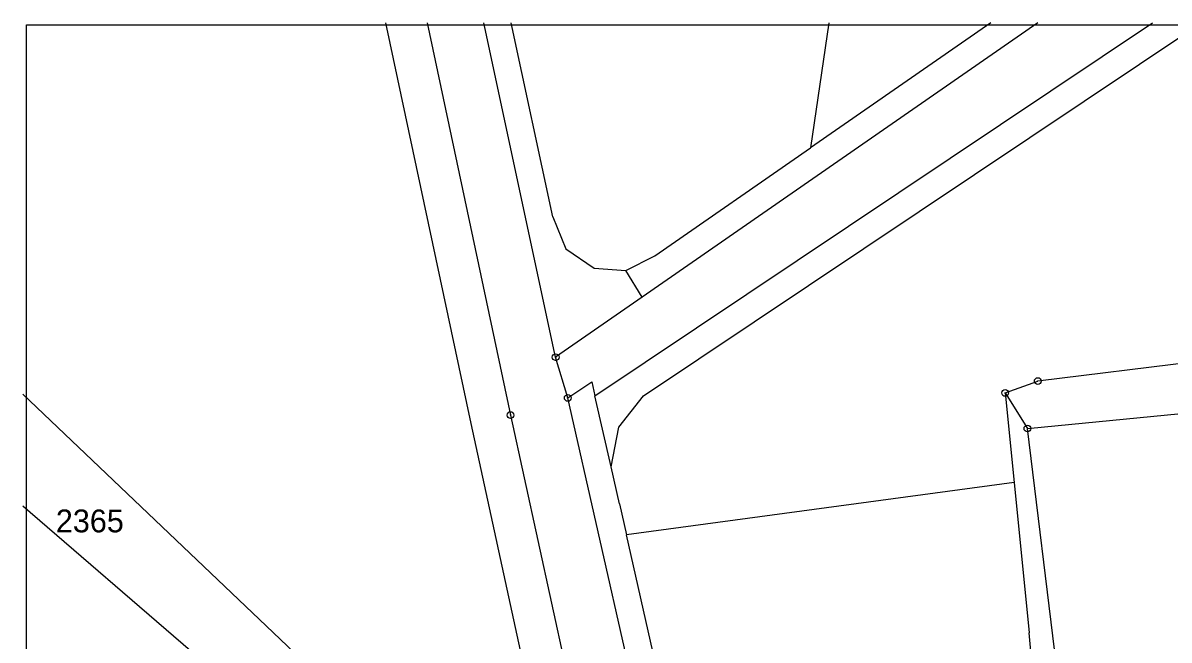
# Model space of a CAD drawing. Extents: x -566461 to -565198, y -1096301 to -1095707.
# Drawn here: x -566458.9 to -566288.3, y -1095798.6 to -1095706.8 of the extents above; entities that cross this region are included whole.
import ezdxf

# ---------------------------------------------------------------- set-up
doc = ezdxf.new("R2010")
doc.units = 0
for name, color, linetype in [('Vrstva 1', 7, 'Continuous'), ('Vrstva 18', 7, 'Continuous'), ('Vrstva 24', 7, 'Continuous'), ('Vrstva 63', 7, 'Continuous')]:
    doc.layers.add(name, color=color, linetype=linetype)

msp = doc.modelspace()

# ---------------------------------------------------------------- linework, layer by layer
at = {"layer": 'Vrstva 1'}
for p, q in [((-566392.21, -1095766.39), (-566404.9, -1095706.75)), ((-566398.76, -1095706.75), (-566386.34, -1095765.13)), ((-566379.63, -1095756.52), (-566390.34, -1095706.75)), ((-566380.04, -1095735.62), (-566386.25, -1095706.75)), ((-566373.79, -1095762.26), (-566290.81, -1095706.75)), ((-566307.87, -1095706.75), (-566366.74, -1095747.58)), ((-566366.58, -1095762.27), (-566283.62, -1095706.75)), ((-566338.96, -1095706.75), (-566341.69, -1095725.34)), ((-566314.89, -1095706.75), (-566341.69, -1095725.34)), ((-566364.89, -1095741.43), (-566341.69, -1095725.34)), ((-566380.04, -1095735.62), (-566378.1, -1095740.37)), ((-566378.1, -1095740.37), (-566373.9, -1095743.25)), ((-566369.18, -1095743.6), (-566364.89, -1095741.43)), ((-566373.9, -1095743.25), (-566369.18, -1095743.6)), ((-566366.74, -1095747.58), (-566369.18, -1095743.6)), ((-566366.74, -1095747.58), (-566379.63, -1095756.52)), ((-566377.83, -1095762.58), (-566379.63, -1095756.52)), ((-566277.86, -1095756.39), (-566307.89, -1095760.07)), ((-566377.83, -1095762.58), (-566374.26, -1095760.19)), ((-566374.26, -1095760.19), (-566373.79, -1095762.26)), ((-566312.74, -1095761.84), (-566307.89, -1095760.07)), ((-566458.91, -1095762.04), (-566383.43, -1095833.87)), ((-566312.74, -1095761.84), (-566309.42, -1095767.13)), ((-566312.74, -1095761.84), (-566311.41, -1095775.18)), ((-566342.24, -1095919.36), (-566377.83, -1095762.58)), ((-566371.39, -1095772.85), (-566373.79, -1095762.26)), ((-566370.23, -1095766.91), (-566366.58, -1095762.27)), ((-566386.34, -1095765.13), (-566359.94, -1095886.56)), ((-566309.42, -1095767.13), (-566276.83, -1095763.96)), ((-566376.68, -1095837.78), (-566392.21, -1095766.39)), ((-566371.39, -1095772.85), (-566370.23, -1095766.91)), ((-566299.74, -1095846.36), (-566309.42, -1095767.13)), ((-566370.14, -1095778.36), (-566371.39, -1095772.85)), ((-566311.41, -1095775.18), (-566369.1, -1095782.94)), ((-566311.41, -1095775.18), (-566309.18, -1095797.54)), ((-566433.97, -1095800.22), (-566458.91, -1095778.71)), ((-566370.14, -1095778.36), (-566369.1, -1095782.94)), ((-566364.8, -1095801.88), (-566369.1, -1095782.94)), ((-566305.22, -1095837.26), (-566309.18, -1095797.54))]:
    msp.add_line(p, q, dxfattribs=at)
at = {"layer": 'Vrstva 24'}
for centre, radius in [((-566379.63, -1095756.52), 0.5), ((-566379.63, -1095756.52), 0.0327), ((-566307.89, -1095760.07), 0.5), ((-566307.89, -1095760.07), 0.0327), ((-566377.83, -1095762.58), 0.5), ((-566312.74, -1095761.84), 0.5), ((-566312.74, -1095761.84), 0.0327), ((-566377.83, -1095762.58), 0.0327), ((-566386.34, -1095765.13), 0.5), ((-566386.34, -1095765.13), 0.0327), ((-566309.42, -1095767.13), 0.5), ((-566309.42, -1095767.13), 0.0327)]:
    msp.add_circle(centre, radius, dxfattribs=at)
at = {"layer": 'Vrstva 63'}
for p, q in [((-566458.38, -1096301.03), (-566458.38, -1095707.03)), ((-566458.38, -1095707.03), (-565198.38, -1095707.03))]:
    msp.add_line(p, q, dxfattribs=at)

# ---------------------------------------------------------------- texts
at = {"layer": 'Vrstva 18'}
msp.add_text('2365', height=3.4, dxfattribs=at).set_placement((-566454.01, -1095782.59))

doc.saveas('drawing.dxf')
